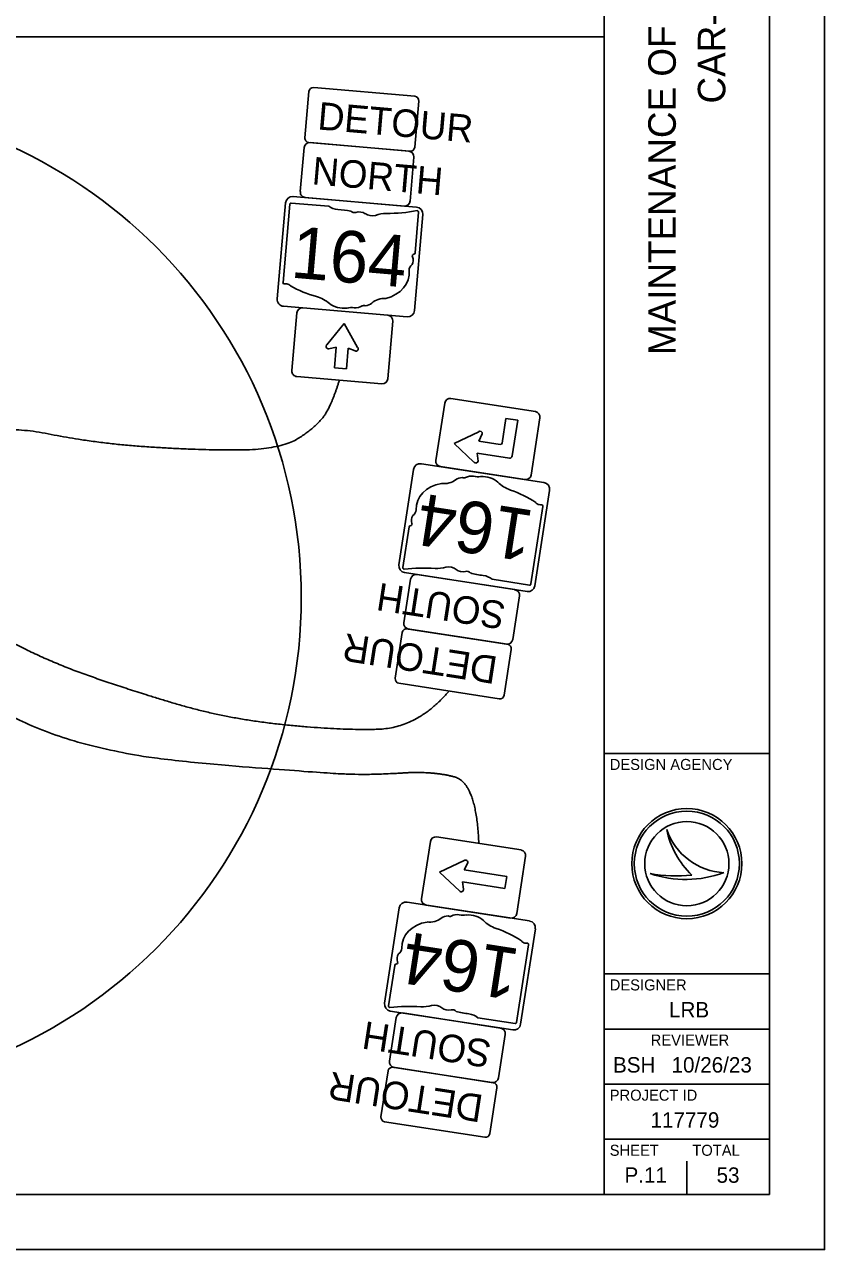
# Model space of a CAD drawing. Extents: x -740 to 1519, y 0 to 440.
# Drawn here: x 534.8 to 680, y 0 to 222.2 of the extents above; entities that cross this region are included whole.
import ezdxf

# ---------------------------------------------------------------- set-up
doc = ezdxf.new("R2010")
doc.units = 0
for name, color, linetype in [('GM_X_Minor_Lake', 7, 'Continuous'), ('GM_X_Minor_River', 7, 'Continuous'), ('GM_X_Section', 7, 'Continuous'), ('SH_Border', 7, 'Continuous'), ('SH_Cut_Line', 7, 'Continuous'), ('SH_Data', 7, 'Continuous')]:
    doc.layers.add(name, color=color, linetype=linetype)

msp = doc.modelspace()

# ---------------------------------------------------------------- linework, layer by layer
at = {"layer": 'GM_X_Minor_Lake'}
for p, q in [((606.84, 63.63), (608.44, 74.01)), ((609.58, 74.85), (624.9, 72.48)), ((625.73, 71.34), (624.13, 60.96)), ((614.57, 70.58), (610.11, 68.44)), ((614.6, 68.86), (615.19, 70.06)), ((610.11, 68.44), (613.77, 65)), ((614.27, 66.69), (621.99, 65.5)), ((614.46, 65.36), (614.27, 66.69)), ((622.32, 67.66), (614.6, 68.86)), ((621.99, 65.5), (622.32, 67.66)), ((622.99, 60.13), (607.67, 62.49))]:
    msp.add_line(p, q, dxfattribs=at)
for centre, radius, start, end in [((609.43, 73.86), 1, 81.2274, 171.2274), ((624.75, 71.49), 1, 351.2274, 81.2274), ((614.81, 70.24), 0.417, 334.0228, 126.237), ((614.05, 65.3), 0.417, 226.6386, 8.432), ((607.83, 63.48), 1, 171.2274, 261.2274), ((623.14, 61.12), 1, 261.2274, 351.2274)]:
    msp.add_arc(centre, radius, start, end, dxfattribs=at)
at = {"layer": 'GM_X_Minor_River'}
for p, q in [((586.6, 200.82), (604.54, 199.27)), ((584.83, 191.94), (585.52, 199.91)), ((605.45, 198.19), (604.76, 190.22)), ((582.91, 189.62), (581.69, 175.45)), ((590, 189.26), (583.16, 189.85)), ((603.68, 189.31), (585.74, 190.86)), ((605.67, 180.79), (606.31, 188.21)), ((605.67, 180.79), (605.67, 180.79)), ((583.29, 159.45), (584.19, 169.91)), ((585.27, 170.82), (600.72, 169.49)), ((589.62, 164.1), (592.81, 167.98)), ((592.81, 167.98), (595.24, 163.67)), ((601.63, 168.41), (600.72, 157.95)), ((591.34, 163.71), (590.03, 163.43)), ((591.02, 159.98), (591.34, 163.71)), ((593.52, 163.53), (593.2, 159.79)), ((594.76, 163.02), (593.52, 163.53)), ((599.64, 157.04), (584.2, 158.37)), ((593.2, 159.79), (591.02, 159.98)), ((611.04, 153.55), (609.44, 143.17)), ((627.5, 152.02), (612.18, 154.38)), ((621.46, 146.31), (622.16, 150.79)), ((622.16, 150.79), (624.32, 150.46)), ((624.32, 150.46), (623.32, 143.97)), ((626.73, 140.5), (628.34, 150.88)), ((612.76, 146.23), (617.22, 148.37)), ((617.87, 147.97), (617.25, 146.65)), ((616.36, 142.85), (612.76, 146.23)), ((622.78, 143.58), (616.91, 144.49)), ((616.91, 144.49), (617.11, 143.03)), ((617.25, 146.65), (621.11, 146.05)), ((622.78, 143.58), (622.78, 143.58)), ((610.27, 142.03), (625.59, 139.67)), ((626.69, 120.75), (628.86, 134.81)), ((604.57, 131.09), (603.44, 123.73)), ((604.57, 131.09), (604.57, 131.09)), ((605.99, 122.46), (623.78, 119.71)), ((603.63, 113.71), (604.85, 121.62)), ((619.64, 121.59), (626.42, 120.54)), ((624.61, 118.57), (623.39, 110.66)), ((622.25, 109.83), (604.46, 112.57)), ((624.09, 41.21), (626.26, 55.28)), ((601.97, 51.55), (600.84, 44.2)), ((601.97, 51.55), (601.97, 51.55)), ((603.39, 42.92), (621.18, 40.17)), ((601.03, 34.18), (602.25, 42.08)), ((617.04, 42.05), (623.82, 41.01)), ((622.01, 39.03), (620.79, 31.13)), ((619.65, 30.29), (601.86, 33.03))]:
    msp.add_line(p, q, dxfattribs=at)
for points in [[(586.4, 210.07), (585.68, 201.7)], [(605.6, 209.22), (587.26, 210.8)], [(605.6, 199.99), (606.32, 208.35)], [(586.4, 200.84), (604.74, 199.26)], [(580.65, 172.48), (582.15, 189.91)], [(583.5, 191.05), (605.92, 189.12)], [(607.06, 187.77), (605.56, 170.33)], [(604.2, 169.19), (581.79, 171.12)], [(606.82, 142.56), (629.05, 139.13)], [(602.72, 124.22), (605.39, 141.52)], [(630.1, 137.71), (627.43, 120.41)], [(626, 119.37), (603.76, 122.8)], [(603.35, 111.93), (602.07, 103.63)], [(622.45, 109.8), (604.27, 112.6)], [(621.84, 100.58), (623.12, 108.88)], [(602.74, 102.72), (620.93, 99.91)], [(604.21, 63.03), (626.45, 59.6)], [(600.12, 44.69), (602.79, 61.98)], [(627.5, 58.17), (624.83, 40.87)], [(623.4, 39.83), (601.16, 43.26)], [(600.75, 32.4), (599.47, 24.09)], [(619.85, 30.26), (601.67, 33.07)], [(619.24, 21.04), (620.52, 29.35)], [(600.14, 23.18), (618.33, 20.38)]]:
    msp.add_lwpolyline(points, dxfattribs=at)
for centre, radius, start, end in [((587.19, 210), 0.8, 85.0733, 175.0733), ((605.53, 208.42), 0.8, 355.0733, 85.0733), ((586.52, 199.82), 1, 85.0733, 175.0733), ((586.47, 201.63), 0.8, 175.0733, 265.0733), ((604.45, 198.28), 1, 355.0733, 85.0733), ((604.81, 200.05), 0.8, 265.0733, 355.0733), ((585.83, 191.85), 1, 175.0733, 265.0733), ((583.4, 189.81), 1.25, 85.0733, 175.0733), ((603.76, 190.31), 1, 265.0733, 355.0733), ((605.81, 187.87), 1.25, 355.0733, 85.0733), ((581.89, 172.37), 1.25, 175.0733, 265.0733), ((585.19, 169.83), 1, 85.0733, 175.0733), ((600.63, 168.5), 1, 355.0733, 85.0733), ((604.31, 170.44), 1.25, 265.0733, 355.0733), ((589.94, 163.83), 0.417, 140.4846, 282.2779), ((594.92, 163.41), 0.417, 247.8687, 40.0829), ((584.28, 159.37), 1, 175.0733, 265.0733), ((599.73, 158.04), 1, 265.0733, 355.0733), ((612.03, 153.4), 1, 81.2274, 171.2274), ((627.35, 151.03), 1, 351.2274, 81.2274), ((617.46, 148.04), 0.417, 351.2258, 126.2273), ((621.16, 146.36), 0.312, 261.2274, 351.2274), ((606.62, 141.33), 1.25, 81.2274, 171.2274), ((610.43, 143.02), 1, 171.2274, 261.2274), ((616.7, 143.1), 0.417, 216.2276, 351.2258), ((622.85, 144.04), 0.469, 261.2274, 351.2274), ((625.75, 140.66), 1, 261.2274, 351.2274), ((628.86, 137.9), 1.25, 351.2274, 81.2274), ((603.96, 124.03), 1.25, 171.2274, 261.2274), ((605.84, 121.47), 1, 81.2274, 171.2274), ((626.19, 120.6), 1.25, 261.2274, 351.2274), ((623.63, 118.72), 1, 351.2274, 81.2274), ((604.62, 113.56), 1, 171.2274, 261.2274), ((604.14, 111.81), 0.8, 81.2274, 171.2274), ((622.41, 110.82), 1, 261.2274, 351.2274), ((622.33, 109.01), 0.8, 351.2274, 81.2274), ((602.86, 103.51), 0.8, 171.2274, 261.2274), ((621.05, 100.7), 0.8, 261.2274, 351.2274), ((604.02, 61.79), 1.25, 81.2274, 171.2274), ((626.26, 58.36), 1.25, 351.2274, 81.2274), ((601.36, 44.5), 1.25, 171.2274, 261.2274), ((603.24, 41.93), 1, 81.2274, 171.2274), ((621.03, 39.18), 1, 351.2274, 81.2274), ((623.59, 41.06), 1.25, 261.2274, 351.2274), ((602.02, 34.02), 1, 171.2274, 261.2274), ((601.54, 32.27), 0.8, 81.2274, 171.2274), ((619.81, 31.28), 1, 261.2274, 351.2274), ((619.73, 29.47), 0.8, 351.2274, 81.2274), ((600.26, 23.97), 0.8, 171.2274, 261.2274), ((618.45, 21.17), 0.8, 261.2274, 351.2274)]:
    msp.add_arc(centre, radius, start, end, dxfattribs=at)
for centre, major_axis, start_param, end_param in [((583.18, 189.63), (0.271, -0.023), 1.712693, 3.28349), ((591.77, 190.77), (2.62, -0.23), 4.042523, 4.731795), ((591.81, 181.08), (9.42, -0.81), 1.404758, 1.657858), ((594.62, 188.72), (0.757, -0.065), 3.836095, 5.185415), ((595.59, 186.98), (1.57, -0.14), 0.950623, 2.079405), ((597.82, 189.06), (1.89, -0.16), 4.081561, 5.145723), ((600.75, 183.97), (4.98, -0.43), 1.699011, 2.107814), ((599.63, 207.9), (24.76, -2.13), 4.814394, 5.042369), ((606.05, 188.26), (0.26, -0.022), 6.141152, 7.989035), ((602.92, 179.53), (2.41, -0.21), 5.934695, 6.695948), ((605.56, 180.25), (0.402, -0.035), 1.883978, 3.671073), ((605.39, 180.79), (0.278, -0.024), 5.05454, 6.418171), ((606.34, 177.61), (1.76, -0.15), 2.387724, 3.262537), ((598.39, 177.34), (6.19, -0.53), 5.101752, 6.440018), ((581.95, 175.39), (0.273, -0.024), 3.00124, 4.508301), ((582.12, 176.84), (2.08, -0.18), 4.665946, 4.897461), ((582.35, 174.57), (0.751, -0.065), 0.519207, 1.627899), ((592.93, 186.49), (17.88, -1.54), 4.195997, 4.488961), ((586.03, 168.66), (5.6, -0.48), 0.823519, 1.323587), ((592.55, 173.62), (3.55, -0.31), 4.026481, 4.996735), ((594.77, 172.35), (1.89, -0.16), 4.691044, 5.507374), ((596.36, 170.83), (0.533, -0.046), 1.147584, 2.315152), ((596.3, 172.8), (2, -0.17), 4.937069, 5.64225), ((600.38, 169.83), (3.39, -0.29), 1.647645, 2.488434), ((594.18, 168.54), (2.92, -0.25), 1.495662, 1.94098), ((614.46, 138.43), (-1.98, 0.31), 4.937069, 5.64225), ((614.53, 140.4), (-0.528, 0.082), 1.147584, 2.315152), ((616.02, 138.78), (-1.88, 0.29), 4.691044, 5.507374), ((616.86, 142.55), (-2.89, 0.45), 1.495662, 1.94098), ((618.15, 137.37), (-3.52, 0.54), 4.026481, 4.996735), ((612.07, 134.04), (-6.14, 0.95), 5.101752, 6.440018), ((610.59, 141.68), (-3.36, 0.52), 1.647645, 2.488434), ((624.99, 141.88), (-5.55, 0.86), 0.823519, 1.323587), ((616.9, 124.55), (-17.74, 2.74), 4.195997, 4.488961), ((604.12, 134.31), (-1.74, 0.27), 2.387724, 3.262537), ((628.25, 135.74), (-0.745, 0.115), 0.519207, 1.627899), ((628.33, 133.45), (-2.07, 0.32), 4.665946, 4.897461), ((628.6, 134.89), (-0.271, 0.042), 3.00124, 4.508301), ((604.85, 131.08), (-0.276, 0.043), 5.05454, 6.418171), ((604.71, 131.62), (-0.399, 0.062), 1.883978, 3.671073), ((607.4, 132.16), (-2.4, 0.37), 5.934695, 6.695948), ((603.69, 123.66), (-0.258, 0.04), 6.141152, 7.989035), ((608.78, 103.63), (-24.56, 3.79), 4.814394, 5.042369), ((609.27, 127.59), (-4.94, 0.76), 1.699011, 2.107814), ((611.85, 122.32), (-1.88, 0.29), 4.081561, 5.145723), ((614.21, 124.23), (-1.56, 0.24), 0.950623, 2.079405), ((615.06, 122.44), (-0.751, 0.116), 3.836095, 5.185415), ((618.38, 129.87), (-9.34, 1.44), 1.404758, 1.657858), ((617.77, 120.21), (-2.6, 0.4), 4.042523, 4.731795), ((626.42, 120.76), (-0.268, 0.041), 1.712693, 3.28349), ((607.99, 62.14), (-3.36, 0.52), 1.647645, 2.488434), ((611.86, 58.9), (-1.98, 0.31), 4.937069, 5.64225), ((611.93, 60.86), (-0.528, 0.082), 1.147584, 2.315152), ((613.42, 59.24), (-1.88, 0.29), 4.691044, 5.507374), ((614.26, 63.01), (-2.89, 0.45), 1.495662, 1.94098), ((615.55, 57.83), (-3.52, 0.54), 4.026481, 4.996735), ((609.47, 54.51), (-6.14, 0.95), 5.101752, 6.440018), ((622.39, 62.34), (-5.55, 0.86), 0.823519, 1.323587), ((614.3, 45.02), (-17.74, 2.74), 4.195997, 4.488961), ((625.65, 56.2), (-0.745, 0.115), 0.519207, 1.627899), ((625.73, 53.92), (-2.07, 0.32), 4.665946, 4.897461), ((604.8, 52.62), (-2.4, 0.37), 5.934695, 6.695948), ((601.52, 54.77), (-1.74, 0.27), 2.387724, 3.262537), ((626, 55.35), (-0.271, 0.042), 3.00124, 4.508301), ((602.25, 51.54), (-0.276, 0.043), 5.05454, 6.418171), ((602.11, 52.08), (-0.399, 0.062), 1.883978, 3.671073), ((601.09, 44.13), (-0.258, 0.04), 6.141152, 7.989035), ((606.18, 24.1), (-24.56, 3.79), 4.814394, 5.042369), ((606.67, 48.05), (-4.94, 0.76), 1.699011, 2.107814), ((609.25, 42.78), (-1.88, 0.29), 4.081561, 5.145723), ((611.61, 44.7), (-1.56, 0.24), 0.950623, 2.079405), ((612.46, 42.9), (-0.751, 0.116), 3.836095, 5.185415), ((615.78, 50.33), (-9.34, 1.44), 1.404758, 1.657858), ((615.17, 40.67), (-2.6, 0.4), 4.042523, 4.731795), ((623.82, 41.22), (-0.268, 0.041), 1.712693, 3.28349)]:
    msp.add_ellipse(centre, major_axis=major_axis, ratio=0.8, start_param=start_param, end_param=end_param, dxfattribs=at)
at = {"layer": 'GM_X_Section'}
msp.add_line((30, 220), (640, 220), dxfattribs=at)
at = {"layer": 'SH_Border'}
for p, q in [((640, 10), (640, 430)), ((640, 90), (670, 90)), ((640, 50), (670, 50)), ((640, 40), (670, 40)), ((640, 30), (670, 30)), ((640, 20), (670, 20))]:
    msp.add_line(p, q, dxfattribs=at)
msp.add_lwpolyline([(30, 430), (670, 430), (670, 10), (30, 10)], close=True, dxfattribs=at)
at = {"layer": 'SH_Cut_Line'}
msp.add_lwpolyline([(0, 0), (680, 0), (680, 440), (0, 440)], close=True, dxfattribs=at)
at = {"layer": 'SH_Data'}
for p, q in [((651.35, 76.19), (651.35, 76.19)), ((655, 70), (655, 70)), ((648.34, 68.19), (648.34, 68.19)), ((661.75, 68.37), (661.75, 68.37)), ((655, 10), (655, 16)), ((647.5, 13.5), (647.5, 13.5))]:
    msp.add_line(p, q, dxfattribs=at)
for centre, radius in [((495, 118.25), 90), ((655, 70), 10), ((655, 70), 9.54), ((655, 70), 9.54), ((655, 70), 7.64)]:
    msp.add_circle(centre, radius, dxfattribs=at)
for centre, radius, start, end in [((662.32, 79.95), 11.6, 198.9257, 198.9319), ((666.93, 79.4), 15.91, 191.6379, 191.6421), ((662.32, 79.95), 11.6, 198.9319, 267.1657), ((666.93, 79.4), 15.91, 191.6421, 226.0947), ((654.79, 87.4), 20.26, 251.4576, 290.0832), ((652.96, 93.09), 25.32, 259.4964, 259.4995), ((654.79, 87.4), 20.26, 251.4527, 251.4576), ((652.96, 93.09), 25.32, 259.4995, 276.6672)]:
    msp.add_arc(centre, radius, start, end, dxfattribs=at)
for points in [[(591.92, 157.7), (590.63, 153.52), (588.03, 149.49), (581.37, 145.11), (566.15, 145.01), (547.53, 146.27), (529.8, 149.82), (516.16, 144.08), (497.29, 136.28)], [(611.83, 101.32), (606.08, 94.56), (591.43, 94.2), (571.11, 96.35), (552.94, 101.78), (538.84, 106.8), (525.44, 113.83), (505.79, 127.29), (491.48, 137.82)], [(617.24, 73.66), (616.8, 84.59), (609.03, 86.82), (597.53, 86.07), (588.48, 86.45), (547, 89.84), (521.97, 101.64), (507.45, 115.64), (500.62, 121.91), (490.75, 133.23)]]:
    msp.add_open_spline(points, degree=2, dxfattribs=at)

# ---------------------------------------------------------------- texts
at = {"layer": 'GM_X_Minor_River'}
for s, height, rotation, p in [('DETOUR', 5, 355.0733, (587.85, 203.22)), ('NORTH', 5, 355.0733, (586.82, 193.27)), ('164', 9.375, 355.0733, (582.92, 176.35)), ('164', 9.375, 171.2274, (627.57, 134)), ('SOUTH', 5, 171.2274, (622.32, 117.41)), ('DETOUR', 5, 171.2274, (620.85, 107.51)), ('164', 9.375, 171.2274, (624.97, 54.46)), ('SOUTH', 5, 171.2274, (619.72, 37.87)), ('DETOUR', 5, 171.2274, (618.25, 27.98))]:
    msp.add_text(s, height=height, rotation=rotation, dxfattribs=at).set_placement(p)
at = {"layer": 'SH_Data'}
for s, p in [('MAINTENANCE OF TRAFFIC - DETOUR INTERSECTION DETAILS', (653, 162.26)), ('CAR-164-10.22 & CAR-164-11.98', (662, 207.91))]:
    msp.add_text(s, height=5, rotation=90, dxfattribs=at).set_placement(p)
for s, height, p in [('DESIGN AGENCY', 2, (641, 87)), ('DESIGNER', 2, (641, 47)), ('LRB', 2.8, (651.77, 42.1)), ('REVIEWER', 2, (648.44, 37)), ('BSH', 2.8, (641.6, 32.1)), ('10/26/23', 2.8, (652.23, 32.1)), ('PROJECT ID', 2, (641, 27)), ('117779', 2.8, (648.41, 22.1)), ('SHEET', 2, (641, 17)), ('TOTAL', 2, (656, 17)), ('P.11', 2.8, (643.69, 12.1)), ('53', 2.8, (660.4, 12.1))]:
    msp.add_text(s, height=height, dxfattribs=at).set_placement(p)

doc.saveas('drawing.dxf')
